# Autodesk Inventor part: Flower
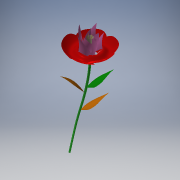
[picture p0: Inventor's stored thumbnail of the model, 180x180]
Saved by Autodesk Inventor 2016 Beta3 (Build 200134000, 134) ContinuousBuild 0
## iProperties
Created: 2006-10
Document SubType Name: Modeling
Designer: Autodesk, Inc.
Density: 1 g/cm^3
Material: Generic
Appearance: Default
Author: Autodesk, Inc.
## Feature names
1. Circular Pattern2
2. Rectangular Pattern1
## Parameters: d0 = 63.5 mm, d3 = 0, d9 = 0, d10 = 0, d11 = 2.02683 mm, d13 = 63.5 mm, d15 = 42.60584 mm, d17 = 0, d18 = 90 deg, d19 = 90 deg, d24 = 47.625 mm, d25 = 7.5 mm, d26 = 16.129 mm, d27 = 5.84866 mm, d28 = 5.08 mm, d31 = 0, d32 = 90 deg, d33 = 76.2 mm, d34 = 5 mm, d35 = 12.7 mm, d36 = 15 deg, d46 = 0, d47 = 90 deg, d48 = 0, d49 = 90 deg, d50 = 0, d51 = 90 deg, d53 = 360 deg, d55 = 25.4 mm, d56 = 2.5 mm, d57 = 25.4 mm, d58 = 20 deg, d59 = 88.9 mm, d60 = 36 deg, d61 = 0, d62 = 90 deg, d63 = 0, d64 = 90 deg, d65 = 0, d66 = 90 deg, d67 = 38.1 mm, d68 = 2.5 mm, d69 = 38.1 mm, d70 = 20 deg, d71 = 0, d72 = 76.2 mm, d73 = 0, d74 = 0.254 mm, d75 = 0, d76 = 3.81 mm, d79 = 38.1 mm, d80 = 5.08 mm, d81 = 5.08 mm, d82 = 6.35 mm, d83 = 0, d84 = 90 deg, d85 = 33.02 mm, d86 = 12.7 mm, d88 = -0.03491 mm, d89 = 0, d90 = 90 deg, d91 = 0, d92 = 90 deg, d93 = 0, d94 = 90 deg, d95 = 0, d96 = 90 deg, d97 = 38.1 mm, d100 = 81.28 mm, d101 = 0, d102 = 90 deg, d103 = 0, d104 = 90 deg, d105 = 0, d106 = 90 deg, d107 = 0, d108 = 90 deg, d109 = 50.8 mm, d110 = 0, d111 = 0, d112 = 0
